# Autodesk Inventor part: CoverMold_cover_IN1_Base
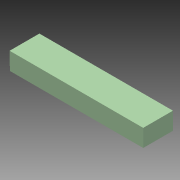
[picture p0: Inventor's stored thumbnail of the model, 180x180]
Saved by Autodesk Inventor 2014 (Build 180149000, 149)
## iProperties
Created: 2009-12
Part Number: CoverMold_cover_IN1_Base
Document SubType Name: Modeling
Designer: gaom
Density: 1 g/cm^3
Material: Generic
Appearance: Green Pastel
Author: gaom
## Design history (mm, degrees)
workplane "Work Plane1"
sketch "Sketch1"
  geometry: L1 (0, 0)-(3.5, 0) reference; L2 (-3.5, -6)-(3.5, -6); L3 (3.5, -6)-(3.5, 6); L4 (3.5, 6)-(-3.5, 6); L5 (-3.5, 6)-(-3.5, -6)
  constraints: 10 end point, 2 horizontal, 1 perpendicular, 1 other
  dimensions: "d0" = 12 distance between parallel lines of L4 L2; "d1" = 7 distance between parallel lines of L5 L3; "d2" = 3.5 distance from line of L5 L1.start (= 0.5 x d1); "d3" = 6 distance from line of L2 L1.start (= 0.5 x d0); "d4" = 90 deg angle of L3 L1
extrude "Extrusion1" join sketch "Sketch1" distance "d5" = 55; taper "d6" = 0 deg
feature "Sculpt1"
body "Solid1"
feature "Surface1"
body "Srf1"
